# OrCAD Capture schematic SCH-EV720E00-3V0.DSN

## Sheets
1 Others: size C; title: EV720E00_Others; rev: 1.0; note: <>
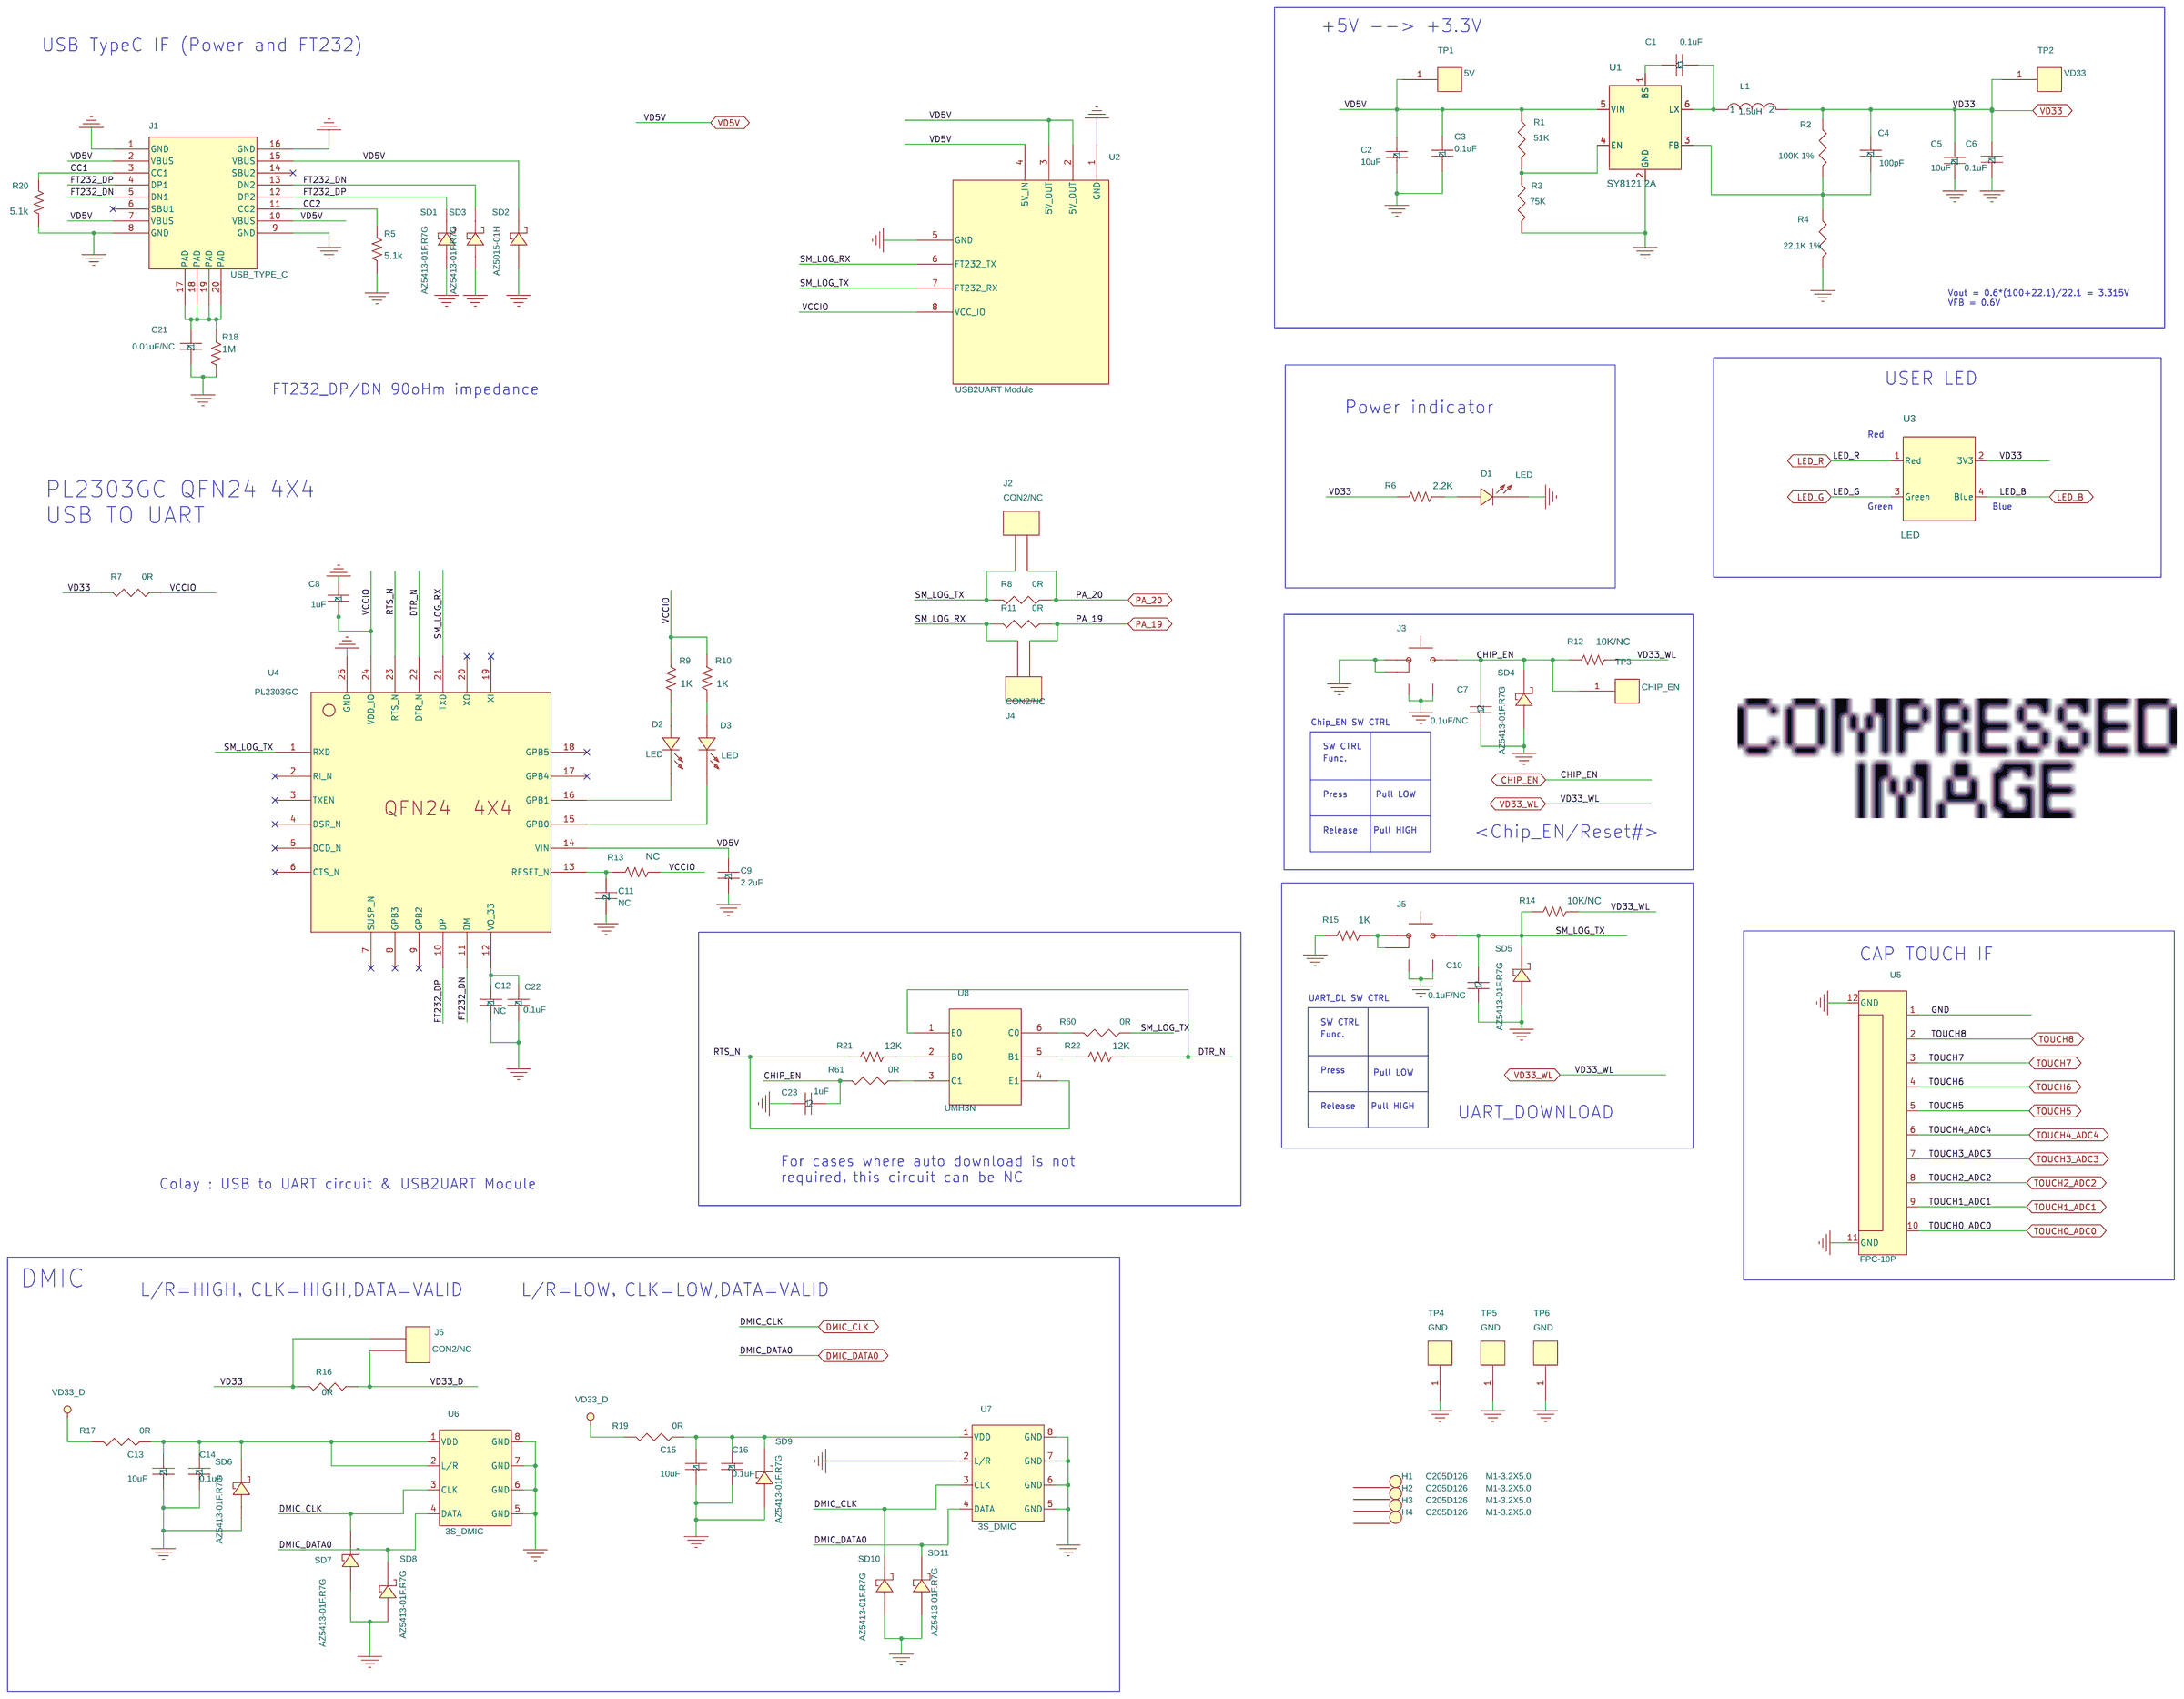
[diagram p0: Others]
2 Module: size C; title: EV720E00
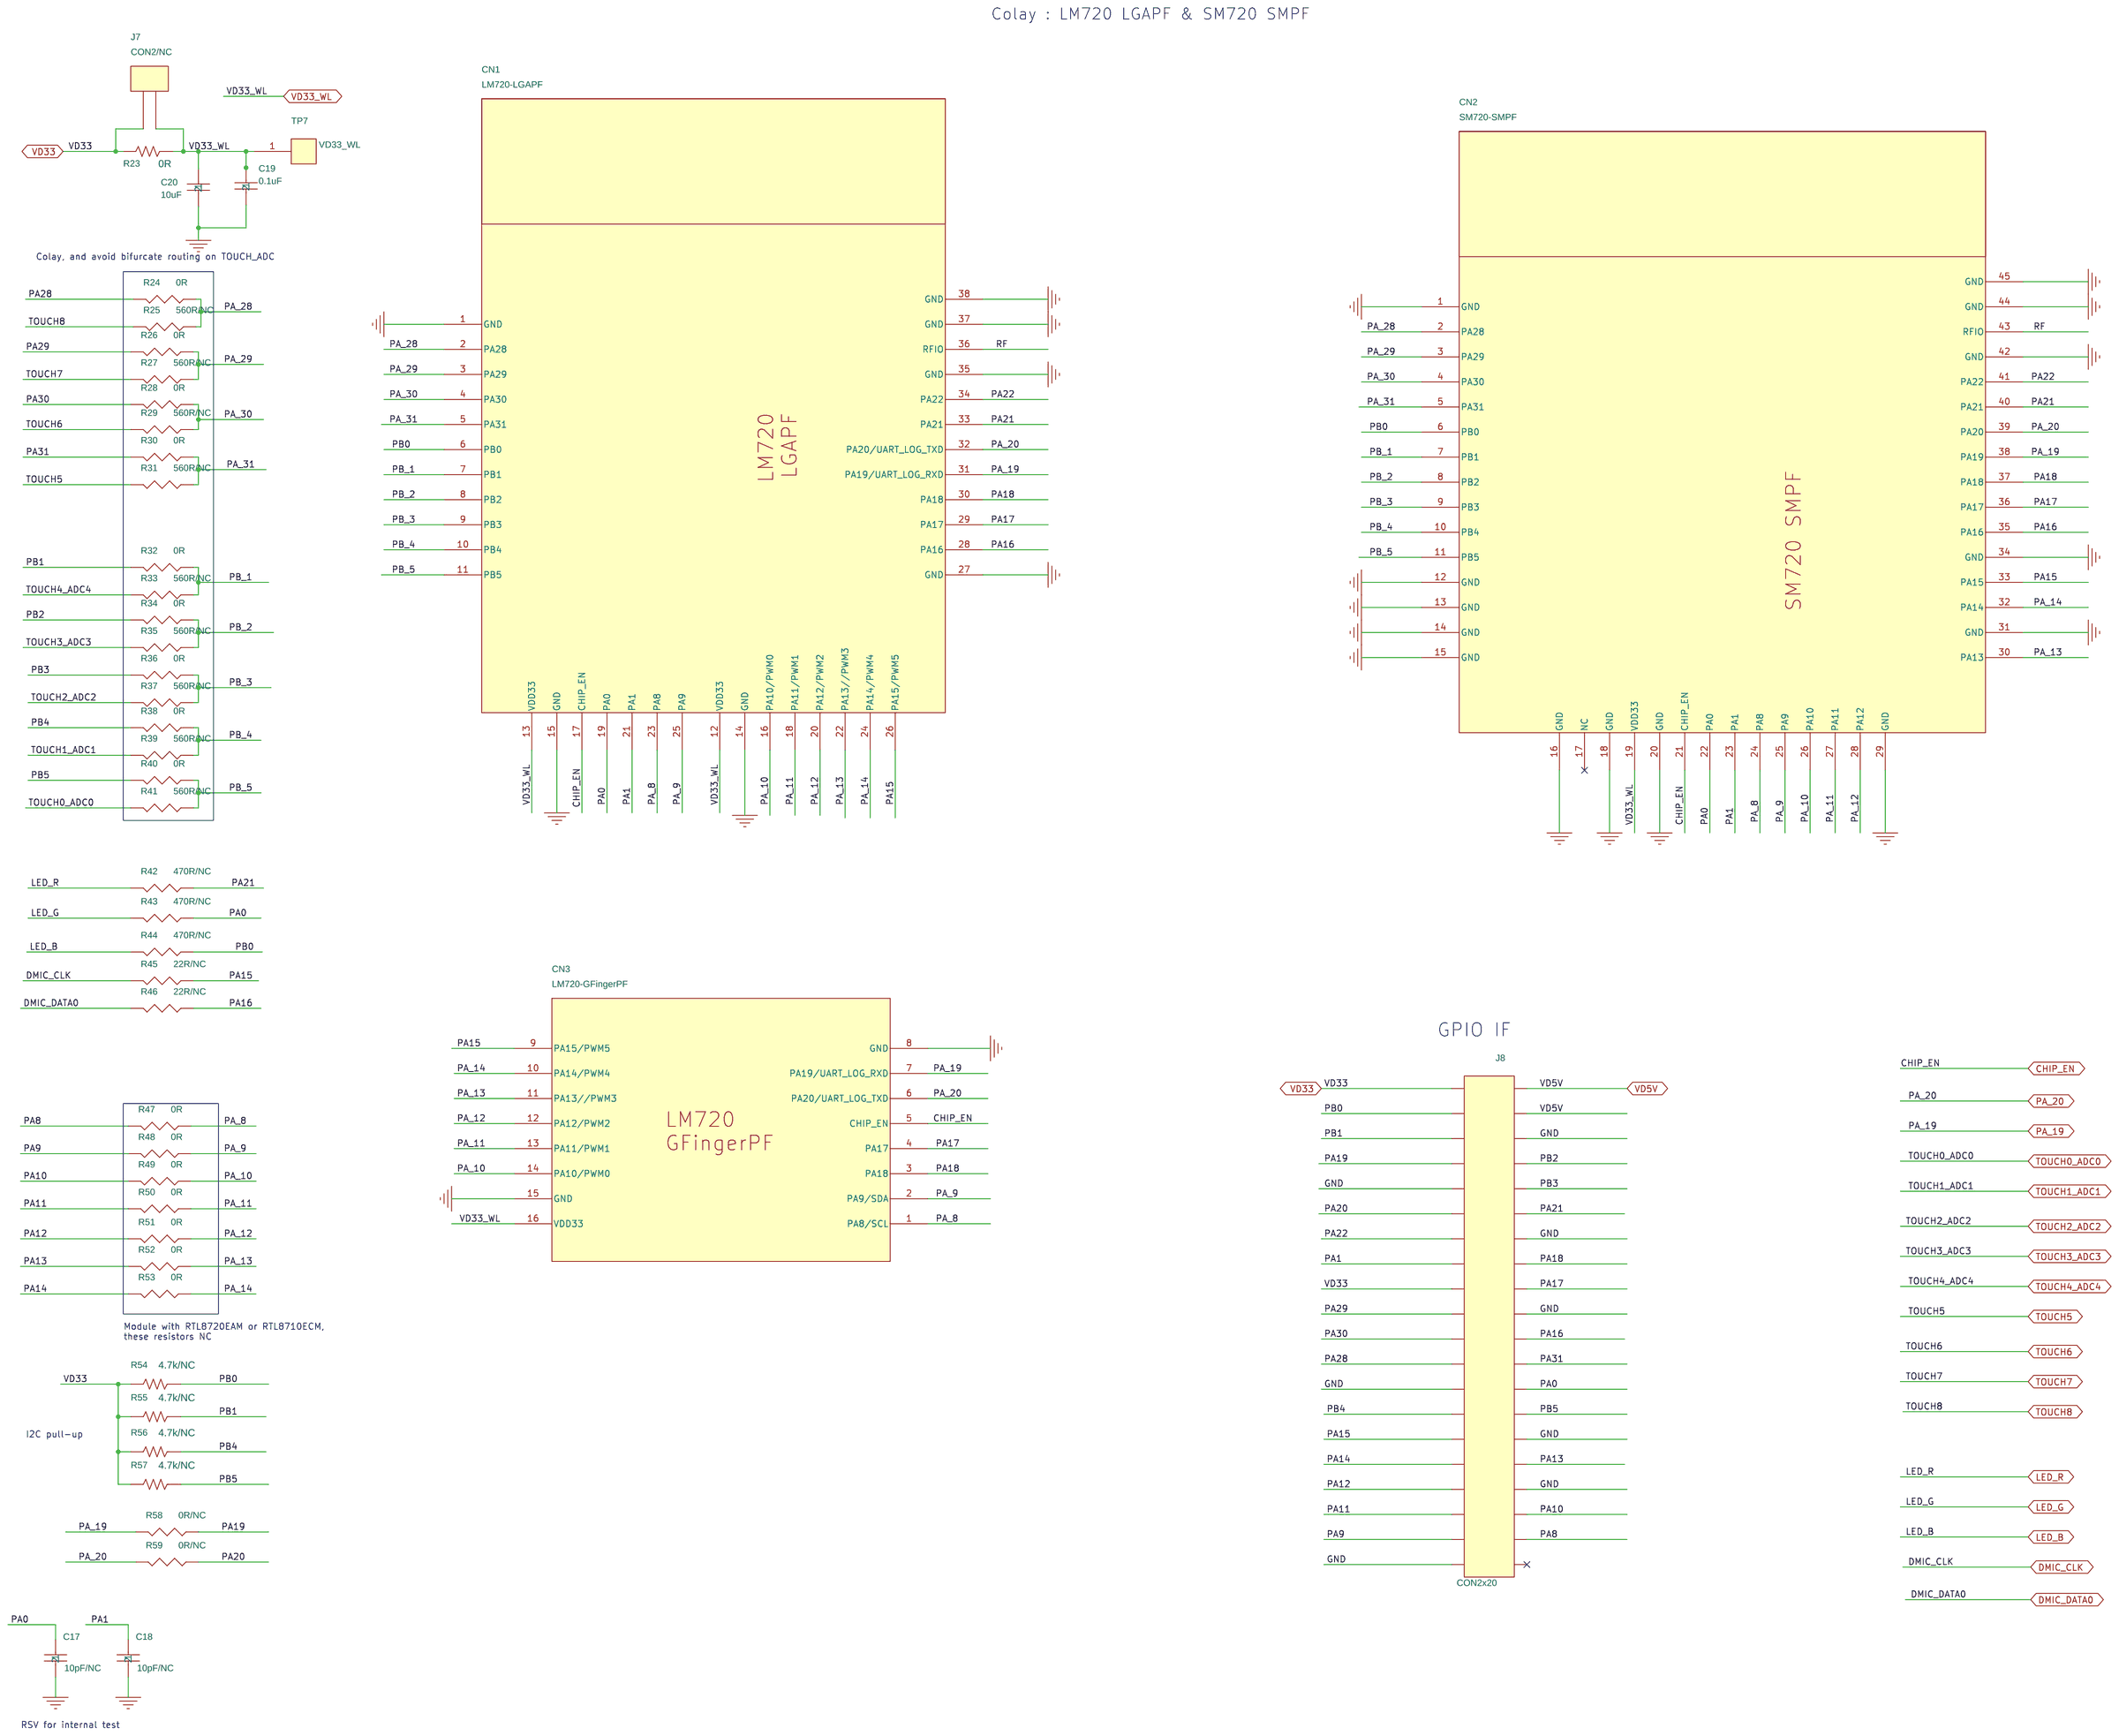
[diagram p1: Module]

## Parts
sheet Module
C17  10pF/NC  [C0402]
C18  10pF/NC  [C0402]
C19  0.1uF  [C0402]
C20  10uF  [C0603]
CN1  LM720-LGAPF  [LM720E00_PF]
CN2  SM720-SMPF  [SM720E00_PF]
CN3  LM720-GFingerPF  [LM720E00_PF_GF]
J7  CON2/NC  [SIP2-2.54]
J8  CON2x20  [SIP20X2-2.54]
R23  0R  [R0805]
R24  0R  [R0402]
R25  560R/NC  [R0402]
R26  0R  [R0402]
R27  560R/NC  [R0402]
R28  0R  [R0402]
R29  560R/NC  [R0402]
R30  0R  [R0402]
R31  560R/NC  [R0402]
R32  0R  [R0402]
R33  560R/NC  [R0402]
R34  0R  [R0402]
R35  560R/NC  [R0402]
R36  0R  [R0402]
R37  560R/NC  [R0402]
R38  0R  [R0402]
R39  560R/NC  [R0402]
R40  0R  [R0402]
R41  560R/NC  [R0402]
R42  470R/NC  [R0402]
R43  470R/NC  [R0402]
R44  470R/NC  [R0402]
R45  22R/NC  [R0402]
R46  22R/NC  [R0402]
R47  0R  [R0402]
R48  0R  [R0402]
R49  0R  [R0402]
R50  0R  [R0402]
R51  0R  [R0402]
R52  0R  [R0402]
R53  0R  [R0402]
R54  4.7k/NC  [R0402]
R55  4.7k/NC  [R0402]
R56  4.7k/NC  [R0402]
R57  4.7k/NC  [R0402]
R58  0R/NC  [R0402]
R59  0R/NC  [R0402]
TP7  VD33_WL  [SIP-1P]
sheet Others
C1  0.1uF  [C0402]
C2  10uF  [C0603]
C3  0.1uF  [C0402]
C4  100pF  [C0402]
C5  10uF  [C0603]
C6  0.1uF  [C0402]
C7  0.1uF/NC  [C0402]
C8  1uF  [C0402]
C9  2.2uF  [C0402]
C10  0.1uF/NC  [C0402]
C11  NC  [C0402]
C12  NC  [C0402]
C13  10uF  [C0603]
C14  0.1uF  [C0402]
C15  10uF  [C0603]
C16  0.1uF  [C0402]
C21  0.01uF/NC  [C0402]
C22  0.1uF  [C0402]
C23  1uF  [C0402]
D1  LED  [LED-0603]
D2  LED  [LED-0603]
D3  LED  [LED-0603]
H1  C205D126  [M1-3.2X5.0]
H2  C205D126  [M1-3.2X5.0]
H3  C205D126  [M1-3.2X5.0]
H4  C205D126  [M1-3.2X5.0]
J1  USB_TYPE_C  [USB-C-SMT]
J2  CON2/NC  [SIP2-2.54]
J3  Reset Button  [SW-PB-5-KAN4548-1]
J4  CON2/NC  [SIP2-2.54]
J5  Reset Button  [SW-PB-5-KAN4548-1]
J6  CON2/NC  [SIP2-2.54]
L1  1.5uH  [MWSA0402]
R1  51K  [R0402]
R2  100K 1%  [R0402]
R3  75K  [R0402]
R4  22.1K 1%  [R0402]
R5  5.1k  [R0402]
R6  2.2K  [R0402]
R7  0R  [R0402]
R8  0R  [R0402]
R9  1K  [R0402]
R10  1K  [R0402]
R11  0R  [R0402]
R12  10K/NC  [R0402]
R13  NC  [R0402]
R14  10K/NC  [R0402]
R15  1K  [R0402]
R16  0R  [R0402]
R17  0R  [R0402]
R18  1M  [R0402]
R19  0R  [R0402]
R20  5.1k  [R0402]
R21  12K  [R0402]
R22  12K  [R0402]
R60  0R  [R0402]
R61  0R  [R0402]
SD1  AZ5413-01F.R7G  [TVS-5413-6118-5451_DIR]
SD2  AZ5015-01H  [TVS-5015-101060_DIR]
SD3  AZ5413-01F.R7G  [TVS-5413-6118-5451_DIR]
SD4  AZ5413-01F.R7G  [TVS-5413-6118-5451_DIR]
SD5  AZ5413-01F.R7G  [TVS-5413-6118-5451_DIR]
SD6  AZ5413-01F.R7G  [TVS-5413-6118-5451_DIR]
SD7  AZ5413-01F.R7G  [TVS-5413-6118-5451_DIR]
SD8  AZ5413-01F.R7G  [TVS-5413-6118-5451_DIR]
SD9  AZ5413-01F.R7G  [TVS-5413-6118-5451_DIR]
SD10  AZ5413-01F.R7G  [TVS-5413-6118-5451_DIR]
SD11  AZ5413-01F.R7G  [TVS-5413-6118-5451_DIR]
TP1  5V  [SIP-1P]
TP2  VD33  [SIP-1P]
TP3  CHIP_EN  [SIP-1P]
TP4  GND  [SIP-1P]
TP5  GND  [SIP-1P]
TP6  GND  [SIP-1P]
U1  SY8121 2A  [SOT-23-6]
U2  USB2UART Module  [MODULE_USB_FT232_2]
U3  LED  [LED3-3.5x2.8]
U4  PL2303GC  [UQFN24-4X4-PL2303GC]
U5  FPC-10P  [FPC-10-1mm]
U6  3S_DMIC  [3SM222FMT1KA]
U7  3S_DMIC  [3SM222FMT1KA]
U8  UMH3N  [SOT-363]

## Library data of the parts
C7 C17 C23 = C_1: X7R, ∮10%, 10V; Manufacturer: WALSIN; Part Number: 0402B104K100CT; Unit Price(USD): 0.0008
C6 C18 = C: X7R, ∮10%, 10V; Manufacturer: WALSIN; Part Number: 0402B104K100CT; Unit Price(USD): 0.0008
C16 C19 = C_2: X7R, ∮10%, 10V; Manufacturer: WALSIN; Part Number: 0402B104K100CT; Unit Price(USD): 0.0008
C2 C20 = CAP_NP: Y5V, ∮20%, 6.3; Manufacturer: WALSIN; Part Number: 0805F226Z6R3CT; Unit Price(USD): 0.01921
CN1 = R0402_25.06K_WALSIN
CN2 = R0402_27.06K_WALSIN
CN3 = R0402_23.06K_WALSIN
J2 J4 J6 J7 = CON2
J8 = CON6_2
R6 R9 R10 R13 R18 R21-R23 = RES_V: Manufacturer: WALSIN; Part Number: WR04X4700FTL; Unit Price(USD): 0.00032
R7 R8 R11 R16 R17 R19 R24-R53 R58-R61 = R
R12 R14 R15 R54-R57 = RES_V: Manufacturer: WALSIN; Part Number: WR04X1003FTL; Unit Price(USD): 0.00032
TP1-TP7 = TP
C1 = CAP_NP_5: Y5V, ∮20%, 25V; Manufacturer: WALSIN; Part Number: 0603F104Z250CT; Unit Price(USD): 0.00118
C3 = C_6: X7R, ∮10%, 10V; Manufacturer: WALSIN; Part Number: 0402B104K100CT; Unit Price(USD): 0.0008
C4 = C_7: X7R, ∮10%, 10V; Manufacturer: WALSIN; Part Number: 0402B104K100CT; Unit Price(USD): 0.0008
C5 = C_4: X7R, ∮10%, 10V; Manufacturer: WALSIN; Part Number: 0402B104K100CT; Unit Price(USD): 0.0008
C8 = CAP_NP_4: NPO, ∮10%, 50V; Manufacturer: WALSIN; Part Number: 0402B102K500CT; Unit Price(USD): 0.00076
C9 = CAP_NP_2: NPO, ∮10%, 50V; Manufacturer: WALSIN; Part Number: 0402B102K500CT; Unit Price(USD): 0.00076
C10 = C_5: X7R, ∮10%, 10V; Manufacturer: WALSIN; Part Number: 0402B104K100CT; Unit Price(USD): 0.0008
C11 = CAP_NP_6: NPO, ∮10%, 50V; Manufacturer: WALSIN; Part Number: 0402B102K500CT; Unit Price(USD): 0.00076
C12 = CAP_NP_1: NPO, ∮10%, 50V; Manufacturer: WALSIN; Part Number: 0402B102K500CT; Unit Price(USD): 0.00076
C13 = CAP_NP_8: Y5V, ∮20%, 6.3; Manufacturer: WALSIN; Part Number: 0805F226Z6R3CT; Unit Price(USD): 0.01921
C14 = C_3: X7R, ∮10%, 10V; Manufacturer: WALSIN; Part Number: 0402B104K100CT; Unit Price(USD): 0.0008
C15 = CAP_NP_7: Y5V, ∮20%, 6.3; Manufacturer: WALSIN; Part Number: 0805F226Z6R3CT; Unit Price(USD): 0.01921
C21 = CAP_NP_3: NPO, ∮10%, 50V; Manufacturer: WALSIN; Part Number: 0402B102K500CT; Unit Price(USD): 0.00076
C22 = CAP_NP_9: NPO, ∮10%, 50V; Manufacturer: WALSIN; Part Number: 0402B102K500CT; Unit Price(USD): 0.00076
D1-D3 = LED_0
H1-H4 = HOLE_PTH: FOR PEGATRON ENTEK; Colay_Alternate: N/A; Colay_Group: N/A; Component_Name: TOOLING HOLE C205D126; Data_Sheet: K:\DataSheet\13-MECHANICAL\T-SH00002166.zip; Device: hole_c205d126; Modify_data: 2013/01/17; Optional: N/A; Package_Type: DIP; Part Number: T-SH00002166; Part Type: 13MECHANICAL\HOLE; Subsystem_ID: N/A
J1 = USB_TYPE_C: Manufacturer: Molex; Part Number: 2171790001
J3 J5 = BUTTON_(RST)_0
L1 = INDUCTOR
R1-R4 = RESISTOR
R5 R20 = RES_V: Manufacturer: WALSIN; Part Number: WR04X1002FTL; Unit Price(USD): 0.00032
SD1-SD11 = DIODE_SCHOTTKY_2
U1 = CAT7103_0: ID: A
U2 = USB2UART_0
U3 = CAT7103_1: ID: A
U4 = RL5760_4
U5 = FPC-10P
U6 U7 = 3S_DMIC_2
U8 = LT1084-3_3.3

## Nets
GND: C2.2 C3.2 C5.2 C6.2 C7.1 C8.1 C9.2 C10.1 C11.2 C12.2 C13.2 C14.2 C15.2 C16.2 C17.2 C18.2 C19.2 C20.2 C21.2 C22.2 C23.1 CN1.1(GND) CN1.14(GND) CN1.15(GND) CN1.27(GND) CN1.35(GND) CN1.37(GND) CN1.38(GND) CN2.1(GND) CN2.12(GND) CN2.13(GND) CN2.14(GND) CN2.15(GND) CN2.16(GND) CN2.18(GND) CN2.20(GND) CN2.29(GND) CN2.31(GND) CN2.34(GND) CN2.42(GND) CN2.44(GND) CN2.45(GND) CN3.8(GND) CN3.15(GND) D1.2 J1.1(GND) J1.8(GND) J1.9(GND) J1.16(GND) J3.1 J3.2 J3.4 J3.5 J5.4 J5.5 J8.6 J8.9 J8.14 J8.20 J8.25 J8.30 J8.34 J8.39 R3.2 R4.2 R5.2 R15.1 R18.1 R20.2 SD1.2 SD2.2 SD3.2 SD4.2 SD5.2 SD6.2 SD7.2 SD8.2 SD9.2 SD10.2 SD11.2 TP4.1 TP5.1 TP6.1 U1.2(GND) U2.1(GND) U2.5(GND) U4.25(GND) U5.1 U5.11(GND) U5.12(GND) U6.5(GND) U6.6(GND) U6.7(GND) U6.8(GND) U7.2(L/R) U7.5(GND) U7.6(GND) U7.7(GND) U7.8(GND)
VCCIO: C8.2 R7.1 R9.2 R10.2 R13.1 U2.8(VCC_IO) U4.24(VDD_IO)
CC1: J1.3(CC1) R20.1
CC2: J1.11(CC2) R5.1
CHIP_EN: C7.2 C23.2 CN1.17(CHIP_EN) CN2.21(CHIP_EN) CN3.5(CHIP_EN) J3.3 R12.1 R61.2 SD4.1 TP3.1
DMIC_CLK: R45.2 SD7.1 SD10.1 U6.3(CLK) U7.3(CLK)
DMIC_DATA0: R46.2 SD8.1 SD11.1 U6.4(DATA) U7.4(DATA)
DTR_N: R22.2 U4.22(DTR_N) U8.1(E0)
FT232_DN: J1.5(DN1) J1.13(DN2) SD3.1 U4.11(DM)
FT232_DP: J1.4(DP1) J1.12(DP2) SD1.1 U4.10(DP)
LED_B: R44.2 U3.4(Blue)
LED_G: R43.2 U3.3(Green)
LED_R: R42.2 U3.1(Red)
PA0: C17.1 CN1.19(PA0) CN2.22(PA0) J8.26 R43.1
PA1: C18.1 CN1.21(PA1) CN2.23(PA1) J8.15
PA8: J8.38 R47.2
PA9: J8.37 R48.2
PA10: J8.36 R49.2
PA11: J8.35 R50.2
PA12: J8.33 R51.2
PA13: J8.32 R52.2
PA14: J8.31 R53.2
PA15: CN1.26(PA15/PWM5) CN2.33(PA15) CN3.9(PA15/PWM5) J8.29 R45.1
PA16: CN1.28(PA16) CN2.35(PA16) J8.22 R46.1
PA17: CN1.29(PA17) CN2.36(PA17) CN3.4(PA17) J8.18
PA18: CN1.30(PA18) CN2.37(PA18) CN3.3(PA18) J8.16
PA19: J8.7 R58.1
PA20: J8.11 R59.1
PA21: CN1.33(PA21) CN2.40(PA21) J8.12 R42.1
PA22: CN1.34(PA22) CN2.41(PA22) J8.13
PA28: J8.23 R24.2
PA29: J8.19 R26.2
PA30: J8.21 R28.2
PA31: J8.24 R30.2
PA_8: CN1.23(PA8) CN2.24(PA8) CN3.1(PA8/SCL) R47.1
PA_9: CN1.25(PA9) CN2.25(PA9) CN3.2(PA9/SDA) R48.1
PA_10: CN1.16(PA10/PWM0) CN2.26(PA10) CN3.14(PA10/PWM0) R49.1
PA_11: CN1.18(PA11/PWM1) CN2.27(PA11) CN3.13(PA11/PWM1) R50.1
PA_12: CN1.20(PA12/PWM2) CN2.28(PA12) CN3.12(PA12/PWM2) R51.1
PA_13: CN1.22(PA13//PWM3) CN2.30(PA13) CN3.11(PA13//PWM3) R52.1
PA_14: CN1.24(PA14/PWM4) CN2.32(PA14) CN3.10(PA14/PWM4) R53.1
PA_19: CN1.31(PA19/UART_LOG_RXD) CN2.38(PA19) CN3.7(PA19/UART_LOG_RXD) J4.2 R11.1 R58.2
PA_20: CN1.32(PA20/UART_LOG_TXD) CN2.39(PA20) CN3.6(PA20/UART_LOG_TXD) J2.2 R8.1 R59.2
PA_28: CN1.2(PA28) CN2.2(PA28) R24.1 R25.1
PA_29: CN1.3(PA29) CN2.3(PA29) R26.1 R27.1
PA_30: CN1.4(PA30) CN2.4(PA30) R28.1 R29.1
PA_31: CN1.5(PA31) CN2.5(PA31) R30.1 R31.1
PB0: CN1.6(PB0) CN2.6(PB0) J8.3 R44.1 R54.2
PB1: J8.5 R32.2 R55.2
PB2: J8.8 R34.2
PB3: J8.10 R36.2
PB4: J8.27 R38.2 R56.2
PB5: J8.28 R40.2 R57.2
PB_1: CN1.7(PB1) CN2.7(PB1) R32.1 R33.1
PB_2: CN1.8(PB2) CN2.8(PB2) R34.1 R35.1
PB_3: CN1.9(PB3) CN2.9(PB3) R36.1 R37.1
PB_4: CN1.10(PB4) CN2.10(PB4) R38.1 R39.1
PB_5: CN1.11(PB5) CN2.11(PB5) R40.1 R41.1
RF: CN1.36(RFIO) CN2.43(RFIO)
RTS_N: R21.1 U4.23(RTS_N) U8.4(E1)
SM_LOG_RX: J4.1 R11.2 U2.6(FT232_TX) U4.21(TXD)
SM_LOG_TX: C10.2 J2.1 J5.3 R8.2 R14.1 R60.1 SD5.1 U2.7(FT232_RX) U4.1(RXD)
TOUCH0_ADC0: R41.2 U5.10
TOUCH1_ADC1: R39.2 U5.9
TOUCH2_ADC2: R37.2 U5.8
TOUCH3_ADC3: R35.2 U5.7
TOUCH4_ADC4: R33.2 U5.6
TOUCH5: R31.2 U5.5
TOUCH6: R29.2 U5.4
TOUCH7: R27.2 U5.3
TOUCH8: R25.2 U5.2
VD5V: C2.1 C3.1 C9.1 J1.2(VBUS) J1.7(VBUS) J1.10(VBUS) J1.15(VBUS) J8.2 J8.4 R1.1 SD2.1 TP1.1 U1.5(VIN) U2.2(5V_OUT) U2.3(5V_OUT) U2.4(5V_IN) U4.14(VIN)
VD33: C4.1 C5.1 C6.1 J6.1 J7.1 J8.1 J8.17 L1.2 R2.1 R6.1 R7.2 R16.2 R23.1 R54.1 R55.1 R56.1 R57.1 TP2.1 U3.2(3V3)
VD33_D: J6.2 R16.1 R17.2 R19.2
VD33_WL: C19.1 C20.1 CN1.12(VDD33) CN1.13(VDD33) CN2.19(VDD33) CN3.16(VDD33) J7.2 R12.2 R14.2 R23.2 TP7.1
N16778246: D1.1 R6.2
N16781236: C13.1 C14.1 R17.1 SD6.1 U6.1(VDD) U6.2(L/R)
N16781279: C15.1 C16.1 R19.1 SD9.1 U7.1(VDD)
N16815574: C21.1 J1.17(PAD) J1.18(PAD) J1.19(PAD) J1.20(PAD) R18.2
N16818157: J5.1 J5.2 R15.2
N16820295: C4.2 R2.2 R4.1 U1.3(FB)
N16820332: R1.2 R3.1 U1.4(EN)
N16820414: C1.2 L1.1 U1.6(LX)
N16820466: C1.1 U1.1(BS)
N16838536: C11.1 R13.2 U4.13(RESET_N)
N16838563: D2.1 R9.1
N16838573: D2.2 U4.16(GPB1)
N16838619: D3.1 R10.1
N16838623: D3.2 U4.15(GPB0)
N16838684: C12.1 C22.1 U4.12(VO_33)
N16863995: R61.1 U8.3(C1)
N16864009: R60.2 U8.6(C0)
N16864069: R22.1 U8.5(B1)
N16864071: R21.2 U8.2(B0)

Not connected (* = marked no-connect by the designer): CN2 17(NC)*; H1 1; H2 1; H3 1; H4 1; J1 6(SBU1)* 14(SBU2)*; J8 40*; U4 2(RI_N)* 3(TXEN)* 4(DSR_N)* 5(DCD_N)* 6(CTS_N)* 7(SUSP_N)* 8(GPB3)* 9(GPB2)* 17(GPB4)* 18(GPB5)* 19(XI)* 20(XO)*

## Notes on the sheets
sheet 1
- +5V --> +3.3V
- USB TypeC IF (Power and FT232)
- Vout = 0.6*(100+22.1)/22.1 = 3.315V
  VFB = 0.6V
- USER LED
- FT232_DP/DN 90oHm impedance
- Power indicator
- Red
- PL2303GC QFN24 4X4
  USB TO UART
- Green
- Blue
- Chip_EN SW CTRL
- SW CTRL
- Func.
- Press
- Pull LOW
- Release
- Pull HIGH
- <Chip_EN/Reset#>
- CAP TOUCH IF
- UART_DL SW CTRL
- SW CTRL
- Func.
- Press
- Pull LOW
- Release
- Pull HIGH
- UART_DOWNLOAD
- For cases where auto download is not
  required，this circuit can be NC
- Colay : USB to UART circuit & USB2UART Module
- DMIC
- L/R=HIGH，CLK=HIGH,DATA=VALID      L/R=LOW，CLK=LOW,DATA=VALID
sheet 2
- Colay : LM720 LGAPF & SM720 SMPF
- Colay, and avoid bifurcate routing on TOUCH_ADC
- GPIO IF
- Module with RTL8720EAM or RTL8710ECM,
  these resistors NC
- I2C pull-up
- RSV for internal test
